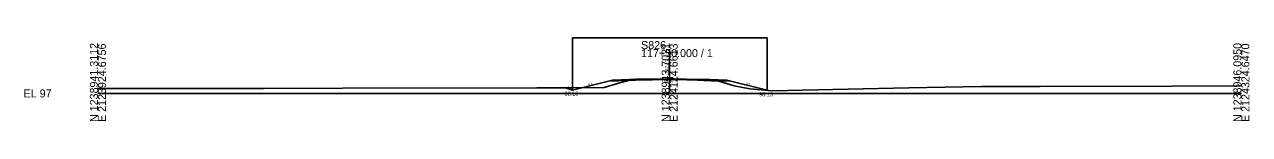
# Model space of a CAD drawing. Extents: x 2119282 to 2119710, y 1215030 to 1220057.
# Drawn here: x 2119281.9 to 2119710.4, y 1216030.1 to 1216059.3 of the extents above; entities that cross this region are included whole.
import ezdxf

# ---------------------------------------------------------------- set-up
doc = ezdxf.new("R2010")
doc.units = 0
for name, color, linetype in [('XS_CELL', 7, 'Continuous'), ('XS_M_DITCH', 7, 'Continuous'), ('XS_P_FINISHED_GRADE', 7, 'Continuous'), ('XS_P_FINISHED_GRADE_ELEV_TX', 7, 'Continuous'), ('XS_P_SUBGRADE_GRANULAR', 7, 'Continuous'), ('XS_P_SUBGRADE_PAVEMENT', 7, 'Continuous'), ('XS_P_TX_DCH', 7, 'Continuous'), ('XS_P_TX_FS_BS', 7, 'Continuous'), ('XS_X_GROUND', 7, 'Continuous'), ('XS_X_GROUND_TX', 7, 'Continuous')]:
    doc.layers.add(name, color=color, linetype=linetype)

msp = doc.modelspace()

# ---------------------------------------------------------------- linework, layer by layer
at = {"layer": 'XS_CELL'}
for p, q in [((2119507.6, 1216039.8), (2119507.6, 1216055.33)), ((2119307.6, 1216039.8), (2119507.6, 1216039.8)), ((2119507.6, 1216039.8), (2119707.6, 1216039.8))]:
    msp.add_line(p, q, dxfattribs=at)
at = {"layer": 'XS_M_DITCH'}
for p, q in [((2119473.6, 1216040.96), (2119473.6, 1216059.26)), ((2119473.6, 1216059.26), (2119541.68, 1216059.26)), ((2119541.68, 1216040.93), (2119541.68, 1216059.26))]:
    msp.add_line(p, q, dxfattribs=at)
at = {"layer": 'XS_P_FINISHED_GRADE'}
for p, q in [((2119487.6, 1216044.45), (2119473.6, 1216040.96)), ((2119493.6, 1216044.69), (2119487.6, 1216044.45)), ((2119495.6, 1216044.73), (2119493.6, 1216044.69)), ((2119507.6, 1216044.97), (2119495.6, 1216044.73)), ((2119507.6, 1216044.97), (2119519.6, 1216044.73)), ((2119519.6, 1216044.73), (2119521.6, 1216044.69)), ((2119521.6, 1216044.69), (2119527.6, 1216044.45)), ((2119527.6, 1216044.45), (2119541.68, 1216040.93)), ((2119473.6, 1216040.96), (2119471.15, 1216041.77))]:
    msp.add_line(p, q, dxfattribs=at)
at = {"layer": 'XS_P_SUBGRADE_GRANULAR'}
for p, q in [((2119493.17, 1216044.39), (2119486.25, 1216044.12)), ((2119522.04, 1216044.39), (2119528.95, 1216044.12))]:
    msp.add_line(p, q, dxfattribs=at)
at = {"layer": 'XS_P_SUBGRADE_PAVEMENT'}
for p, q in [((2119493.6, 1216044.69), (2119493.17, 1216044.39)), ((2119495.61, 1216044.44), (2119493.17, 1216044.39)), ((2119507.6, 1216044.68), (2119495.61, 1216044.44)), ((2119507.6, 1216044.68), (2119519.6, 1216044.44)), ((2119519.6, 1216044.44), (2119522.04, 1216044.39)), ((2119521.6, 1216044.69), (2119522.04, 1216044.39))]:
    msp.add_line(p, q, dxfattribs=at)
at = {"layer": 'XS_X_GROUND'}
for p, q in [((2119484.68, 1216041.89), (2119490.19, 1216043.46)), ((2119490.19, 1216043.46), (2119494.09, 1216044.6)), ((2119494.09, 1216044.6), (2119495.03, 1216044.7)), ((2119495.03, 1216044.7), (2119495.67, 1216044.75)), ((2119495.67, 1216044.75), (2119506.59, 1216044.96)), ((2119506.59, 1216044.96), (2119507.6, 1216044.97)), ((2119507.6, 1216044.97), (2119508.64, 1216044.93)), ((2119508.64, 1216044.93), (2119519.58, 1216044.39)), ((2119519.58, 1216044.39), (2119522.14, 1216044.2)), ((2119522.14, 1216044.2), (2119524.78, 1216044.1)), ((2119524.78, 1216044.1), (2119530.19, 1216042.44)), ((2119307.37, 1216041.54), (2119344, 1216041.55)), ((2119344, 1216041.55), (2119365.47, 1216041.58)), ((2119365.47, 1216041.58), (2119393.12, 1216041.63)), ((2119393.12, 1216041.63), (2119461.19, 1216041.75)), ((2119461.19, 1216041.75), (2119473.67, 1216041.78)), ((2119473.67, 1216041.78), (2119484.68, 1216041.89)), ((2119530.19, 1216042.44), (2119535.63, 1216041.47)), ((2119535.63, 1216041.47), (2119543.49, 1216040.77)), ((2119543.49, 1216040.77), (2119591.29, 1216041.71)), ((2119591.29, 1216041.71), (2119616.68, 1216042.23)), ((2119616.68, 1216042.23), (2119637.18, 1216042.22)), ((2119637.18, 1216042.22), (2119683.37, 1216042.3)), ((2119683.37, 1216042.3), (2119707.37, 1216042.42))]:
    msp.add_line(p, q, dxfattribs=at)

# ---------------------------------------------------------------- texts
at = {"layer": 'XS_CELL'}
for s, p in [('N 1238941.3112', (2119307.6, 1216029.8)), ('E 2123924.6756', (2119310.4, 1216029.8)), ('N 1238943.7031', (2119507.6, 1216029.8)), ('E 2124124.6613', (2119510.4, 1216029.8)), ('N 1238946.0950', (2119707.6, 1216029.8)), ('E 2124324.6470', (2119710.4, 1216029.8))]:
    msp.add_text(s, height=2.8, rotation=90, dxfattribs=at).set_placement(p)
for s, p in [('S826', (2119497.6, 1216055.33)), ('117+50.000 / 1', (2119497.6, 1216052.53)), ('EL 97', (2119281.6, 1216038.4))]:
    msp.add_text(s, height=2.8, dxfattribs=at).set_placement(p)
at = {"layer": 'XS_P_FINISHED_GRADE_ELEV_TX'}
msp.add_text('102.17', height=1.25, rotation=90, dxfattribs=at).set_placement((2119507.22, 1216046.52))
at = {"layer": 'XS_P_TX_DCH'}
for s, p in [('98.16', (2119470.82, 1216039.05)), ('98.13', (2119538.89, 1216038.8))]:
    msp.add_text(s, height=1.4, dxfattribs=at).set_placement(p)
at = {"layer": 'XS_P_TX_FS_BS'}
for s, rotation, p in [('4:1', 14.015, (2119479.11, 1216042.57)), ('4:1', 345.9638, (2119534.27, 1216042.94)), ('3:1', 341.5921, (2119471.67, 1216041.72))]:
    msp.add_text(s, height=0.8, rotation=rotation, dxfattribs=at).set_placement(p)
at = {"layer": 'XS_X_GROUND_TX'}
msp.add_text('102.17', height=1, dxfattribs=at).set_placement((2119504.78, 1216043.48))

doc.saveas('drawing.dxf')
